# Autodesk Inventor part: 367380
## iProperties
Created: 2006-07
Part Number: 367380
Material: A2
Description: Senkschraube
Vendor: Autodesk Inc.
Document SubType Name: Modeling
Standard: DIN 7991
Designer: I.Baliuc
Standards Organization: DIN
Language: de-DE
Size Designation: M6 x 16
Categories: <MemberInstance Version="R10.0.0"><Categories><Category DisplayName="Schrauben" InternalName="e4da775c-781d-43d5-af7c-5136215cf5a6" Mnemonic="FSTN"><Category Di
Density: 8.08 g/cm^3
Abmessung: M6 x 16
Author: T.Messerschmitt
Comments: DIN 7991 - M6 x 16
Revision Number: 367380
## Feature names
1. Körper [Revolution]
2. Loch [Extrusion]
3. Fase1 [Chamfer]
